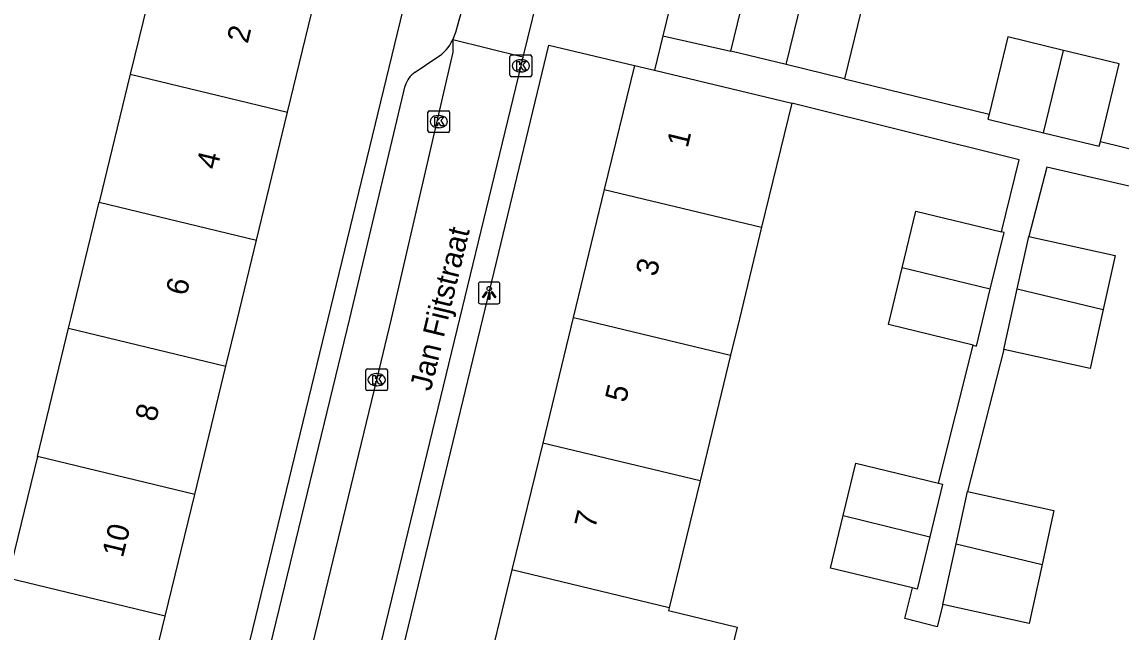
# Model space of a CAD drawing. Extents: x 162812 to 163818, y 381639 to 382470.
# Drawn here: x 163316.1 to 163366.7, y 382235.6 to 382263.7 of the extents above; entities that cross this region are included whole.
import ezdxf

# ---------------------------------------------------------------- set-up
doc = ezdxf.new("R2010")
doc.units = 0
for name, color, linetype in [('IMGEO_Kolk', 7, 'Continuous'), ('IMGEO_Lichtpunt', 7, 'Continuous'), ('IMGEO_Openbare_ruimte_label', 7, 'Continuous'), ('IMGEO_Pand', 7, 'Continuous'), ('IMGEO_Pand_nummerreeks', 7, 'Continuous'), ('IMGEO_Rijbaan_lokaal_open', 7, 'Continuous'), ('IMGEO_Voetpad_open', 7, 'Continuous')]:
    doc.layers.add(name, color=color, linetype=linetype)

msp = doc.modelspace()

# ---------------------------------------------------------------- linework, layer by layer
at = {"layer": 'IMGEO_Kolk'}
for p, q in [((163338.635, 382262.143), (163339.487, 382262.143)), ((163338.56, 382261.217), (163338.56, 382262.069)), ((163339.048, 382261.923), (163339.073, 382261.923)), ((163339.561, 382262.069), (163339.561, 382261.217)), ((163339.487, 382261.143), (163338.635, 382261.143)), ((163339.071, 382261.363), (163339.046, 382261.363)), ((163334.857, 382259.578), (163335.709, 382259.578)), ((163334.782, 382258.652), (163334.782, 382259.504)), ((163335.27, 382259.358), (163335.295, 382259.358)), ((163335.783, 382259.504), (163335.783, 382258.652)), ((163335.709, 382258.578), (163334.857, 382258.578)), ((163335.293, 382258.798), (163335.268, 382258.798)), ((163331.925, 382246.78), (163331.925, 382247.632)), ((163332, 382247.706), (163332.852, 382247.706)), ((163332.413, 382247.486), (163332.438, 382247.486)), ((163332.926, 382247.632), (163332.926, 382246.78)), ((163332.436, 382246.926), (163332.411, 382246.926)), ((163332.852, 382246.706), (163332, 382246.706))]:
    msp.add_line(p, q, dxfattribs=at)
for points in [[(163338.635, 382262.143), (163339.487, 382262.143)], [(163338.56, 382261.217), (163338.56, 382262.069)], [(163338.881, 382261.843), (163339.004, 382261.843), (163339.004, 382261.692), (163339.134, 382261.843), (163339.298, 382261.843), (163339.152, 382261.692), (163339.305, 382261.443), (163339.153, 382261.443), (163339.068, 382261.607), (163339.004, 382261.54), (163339.004, 382261.443), (163338.881, 382261.443), (163338.881, 382261.843)], [(163339.561, 382262.069), (163339.561, 382261.217)], [(163339.487, 382261.143), (163338.635, 382261.143)], [(163334.857, 382259.578), (163335.709, 382259.578)], [(163334.782, 382258.652), (163334.782, 382259.504)], [(163335.103, 382259.278), (163335.226, 382259.278), (163335.226, 382259.127), (163335.356, 382259.278), (163335.52, 382259.278), (163335.374, 382259.127), (163335.527, 382258.878), (163335.375, 382258.878), (163335.29, 382259.042), (163335.226, 382258.975), (163335.226, 382258.878), (163335.103, 382258.878), (163335.103, 382259.278)], [(163335.783, 382259.504), (163335.783, 382258.652)], [(163335.709, 382258.578), (163334.857, 382258.578)], [(163331.925, 382246.78), (163331.925, 382247.632)], [(163332, 382247.706), (163332.852, 382247.706)], [(163332.926, 382247.632), (163332.926, 382246.78)], [(163332.246, 382247.406), (163332.369, 382247.406), (163332.369, 382247.255), (163332.499, 382247.406), (163332.663, 382247.406), (163332.517, 382247.255), (163332.67, 382247.006), (163332.518, 382247.006), (163332.433, 382247.17), (163332.369, 382247.103), (163332.369, 382247.006), (163332.246, 382247.006), (163332.246, 382247.406)], [(163332.852, 382246.706), (163332, 382246.706)]]:
    msp.add_lwpolyline(points, dxfattribs=at)
for centre, start, end in [((163338.637, 382262.067), 91.552, 178.448), ((163338.637, 382262.067), 91.552, 178.448), ((163339.485, 382262.067), 1.552, 88.448), ((163339.485, 382262.067), 1.552, 88.448), ((163338.637, 382261.219), 181.552, 268.448), ((163338.637, 382261.219), 181.552, 268.448), ((163339.485, 382261.219), 271.552, 358.448), ((163339.485, 382261.219), 271.552, 358.448), ((163334.859, 382259.502), 91.552, 178.448), ((163334.859, 382259.502), 91.552, 178.448), ((163335.707, 382259.502), 1.552, 88.448), ((163335.707, 382259.502), 1.552, 88.448), ((163334.859, 382258.654), 181.552, 268.448), ((163334.859, 382258.654), 181.552, 268.448), ((163335.707, 382258.654), 271.552, 358.448), ((163335.707, 382258.654), 271.552, 358.448), ((163332.002, 382247.63), 91.552, 178.448), ((163332.002, 382247.63), 91.552, 178.448), ((163332.85, 382247.63), 1.552, 88.448), ((163332.85, 382247.63), 1.552, 88.448), ((163332.002, 382246.782), 181.552, 268.448), ((163332.002, 382246.782), 181.552, 268.448), ((163332.85, 382246.782), 271.552, 358.448), ((163332.85, 382246.782), 271.552, 358.448)]:
    msp.add_arc(centre, 0.0765, start, end, dxfattribs=at)
for centre, major_axis, ratio, start_param, end_param in [((163339.047, 382261.643), (-0.387, 0.002), 0.722429, 4.712389, 7.853982), ((163339.072, 382261.643), (-0.39, 0.002), 0.717154, 1.570796, 4.712389), ((163335.269, 382259.078), (-0.387, 0.002), 0.722429, 4.712389, 7.853982), ((163335.294, 382259.078), (-0.39, 0.002), 0.717154, 1.570796, 4.712389), ((163332.412, 382247.206), (-0.387, 0.002), 0.722429, 4.712389, 7.853982), ((163332.437, 382247.206), (-0.39, 0.002), 0.717154, 1.570796, 4.712389)]:
    msp.add_ellipse(centre, major_axis=major_axis, ratio=ratio, start_param=start_param, end_param=end_param, dxfattribs=at)
at = {"layer": 'IMGEO_Lichtpunt'}
for p, q in [((163337.103, 382251.599), (163337.103, 382250.792)), ((163337.103, 382251.599), (163337.103, 382250.792)), ((163338.005, 382251.694), (163337.197, 382251.694)), ((163338.005, 382251.694), (163337.197, 382251.694)), ((163338.099, 382250.792), (163338.099, 382251.599)), ((163338.099, 382250.792), (163338.099, 382251.599)), ((163337.197, 382250.698), (163338.005, 382250.698)), ((163337.197, 382250.698), (163338.005, 382250.698))]:
    msp.add_line(p, q, dxfattribs=at)
for points in [[(163337.477, 382251.263), (163337.516, 382251.235), (163337.328, 382250.973), (163337.29, 382251), (163337.477, 382251.263)], [(163337.579, 382251.215), (163337.626, 382251.215), (163337.626, 382250.893), (163337.579, 382250.893), (163337.579, 382251.215)], [(163337.689, 382251.235), (163337.727, 382251.262), (163337.914, 382251), (163337.875, 382250.972), (163337.689, 382251.235)]]:
    msp.add_lwpolyline(points, dxfattribs=at)
msp.add_circle((163337.602, 382251.397), 0.0994, dxfattribs=at)
for centre, start, end in [((163337.197, 382251.599), 90, 180), ((163337.197, 382251.599), 90, 180), ((163338.005, 382251.599), 0, 90), ((163338.005, 382251.599), 0, 90), ((163337.197, 382250.792), 180, 270), ((163337.197, 382250.792), 180, 270), ((163338.005, 382250.792), 270, 0), ((163338.005, 382250.792), 270, 360)]:
    msp.add_arc(centre, 0.0946, start, end, dxfattribs=at)
at = {"layer": 'IMGEO_Pand'}
for points in [[(163322.474, 382266.968), (163321.087, 382261.26)], [(163348.719, 382262.318), (163349.625, 382266.04), (163352.175, 382265.419)], [(163328.325, 382259.517), (163329.707, 382265.204)], [(163351.268, 382261.697), (163352.175, 382265.419)], [(163352.175, 382265.419), (163354.853, 382264.767), (163353.947, 382261.045)], [(163364.033, 382262.354), (163361.469, 382262.974), (163360.607, 382259.413)], [(163351.268, 382261.697), (163348.719, 382262.318)], [(163363.116, 382258.567), (163364.033, 382262.354)], [(163365.731, 382258.157), (163366.597, 382261.733), (163364.033, 382262.354)], [(163344.289, 382261.664), (163342.901, 382255.951)], [(163344.289, 382261.664), (163345.207, 382261.443)], [(163353.947, 382261.045), (163351.268, 382261.697)], [(163321.087, 382261.26), (163319.656, 382255.369)], [(163321.087, 382261.26), (163328.325, 382259.517)], [(163345.207, 382261.443), (163351.528, 382259.924)], [(163351.528, 382259.924), (163350.141, 382254.217)], [(163326.894, 382253.626), (163328.325, 382259.517)], [(163360.607, 382259.413), (163360.552, 382259.188), (163363.116, 382258.567)], [(163363.116, 382258.567), (163365.68, 382257.946), (163365.731, 382258.157)], [(163342.901, 382255.951), (163341.471, 382250.069)], [(163342.901, 382255.951), (163350.141, 382254.217)], [(163318.247, 382249.573), (163318.351, 382250), (163319.656, 382255.369)], [(163319.656, 382255.369), (163326.894, 382253.626)], [(163356.609, 382252.353), (163357.244, 382254.965), (163361.172, 382254.011)], [(163350.141, 382254.217), (163349.116, 382250), (163348.711, 382248.335)], [(163360.663, 382251.368), (163361.298, 382253.98), (163361.172, 382254.011)], [(163325.486, 382247.83), (163326.013, 382250), (163326.894, 382253.626)], [(163361.905, 382251.386), (163362.432, 382253.792)], [(163362.432, 382253.792), (163366.405, 382252.922), (163365.859, 382250.432)], [(163359.868, 382248.795), (163355.975, 382249.741), (163356.609, 382252.353)], [(163360.663, 382251.368), (163356.609, 382252.353)], [(163359.868, 382248.795), (163360.028, 382248.756), (163360.663, 382251.368)], [(163361.293, 382248.59), (163361.905, 382251.386)], [(163361.905, 382251.386), (163365.859, 382250.432)], [(163341.471, 382250.069), (163340.065, 382244.286)], [(163341.471, 382250.069), (163341.76, 382250), (163348.711, 382248.335)], [(163365.859, 382250.432), (163365.265, 382247.72), (163361.293, 382248.59)], [(163316.815, 382243.68), (163318.247, 382249.573)], [(163318.247, 382249.573), (163325.486, 382247.83)], [(163348.711, 382248.335), (163347.306, 382242.552)], [(163324.054, 382241.936), (163325.486, 382247.83)], [(163340.065, 382244.286), (163338.649, 382238.459)], [(163347.306, 382242.552), (163340.065, 382244.286)], [(163316.815, 382243.68), (163315.456, 382238.085)], [(163324.054, 382241.936), (163316.815, 382243.68)], [(163353.892, 382240.958), (163354.478, 382243.368), (163358.281, 382242.443)], [(163347.306, 382242.552), (163345.889, 382236.724)], [(163358.281, 382242.443), (163358.467, 382242.398), (163357.881, 382239.988)], [(163322.694, 382236.341), (163324.054, 382241.936)], [(163359.09, 382239.661), (163359.617, 382242.069)], [(163359.617, 382242.069), (163363.59, 382241.199), (163363.044, 382238.708)], [(163357.077, 382237.631), (163353.306, 382238.548), (163353.892, 382240.958)], [(163353.892, 382240.958), (163357.881, 382239.988)], [(163357.881, 382239.988), (163357.295, 382237.578), (163357.077, 382237.631)], [(163358.478, 382236.867), (163359.09, 382239.661)], [(163359.09, 382239.661), (163363.044, 382238.708)], [(163338.649, 382238.459), (163337.28, 382232.829)], [(163345.889, 382236.724), (163338.649, 382238.459)], [(163363.044, 382238.708), (163362.45, 382235.997), (163358.478, 382236.867)], [(163322.694, 382236.341), (163315.456, 382238.085)], [(163321.25, 382230.399), (163322.694, 382236.341)], [(163345.889, 382236.724), (163345.856, 382236.588), (163349.011, 382235.822), (163347.644, 382230.197), (163344.489, 382230.964)]]:
    msp.add_lwpolyline(points, dxfattribs=at)
at = {"layer": 'IMGEO_Rijbaan_lokaal_open'}
for points in [[(163335.923, 382262.841), (163336.07, 382263.186), (163336.691, 382265.461)], [(163339.789, 382264.679), (163339.145, 382262.043)], [(163335.923, 382262.841), (163335.923, 382262.268), (163333.095, 382250), (163332.423, 382247.206), (163325.569, 382218.972), (163321.838, 382204.251), (163321.731, 382204.132)], [(163339.145, 382262.043), (163335.923, 382262.841)], [(163339.145, 382262.043), (163339.056, 382261.643), (163336.233, 382250), (163331.974, 382232.436), (163324.797, 382202.931)]]:
    msp.add_lwpolyline(points, dxfattribs=at)
at = {"layer": 'IMGEO_Voetpad_open'}
for points in [[(163348.115, 382273.365), (163347.712, 382271.713), (163345.594, 382263.028)], [(163329.707, 382265.204), (163333.628, 382264.215), (163330.176, 382250), (163326.205, 382233.651), (163318.48, 382201.917), (163317.086, 382200.697)], [(163325.68, 382202.052), (163332.984, 382232.131), (163337.307, 382250), (163340.354, 382262.596), (163344.289, 382261.664)], [(163345.594, 382263.028), (163345.207, 382261.443)], [(163345.594, 382263.028), (163348.719, 382262.318)], [(163334.201, 382261.346), (163335.195, 382262.022)], [(163320.747, 382207.042), (163327.149, 382233.422), (163331.183, 382250.016), (163333.742, 382260.717)], [(163353.947, 382261.045), (163360.607, 382259.413)], [(163361.172, 382254.011), (163361.998, 382257.313), (163351.528, 382259.924)], [(163365.731, 382258.157), (163371.902, 382256.645)], [(163372.02, 382254.963), (163363.258, 382256.98), (163362.432, 382253.792)], [(163358.281, 382242.443), (163359.868, 382248.795)], [(163361.293, 382248.59), (163359.617, 382242.069)], [(163358.478, 382236.867), (163358.216, 382235.85), (163356.728, 382236.233), (163357.077, 382237.631)]]:
    msp.add_lwpolyline(points, dxfattribs=at)
for centre, radius, start, end in [((163334.207, 382263.634), 1.89, 301.5194, 335.2135), ((163334.732, 382260.476), 1.019, 121.419, 166.3423)]:
    msp.add_arc(centre, radius, start, end, dxfattribs=at)

# ---------------------------------------------------------------- texts
at = {"layer": 'IMGEO_Openbare_ruimte_label'}
msp.add_text('Jan Fijtstraat', height=1, rotation=76.4084, dxfattribs=at).set_placement((163334.913, 382246.644))
at = {"layer": 'IMGEO_Pand_nummerreeks'}
for s, rotation, p in [('2', 76.3426, (163326.488, 382262.629)), ('1', 76.3388, (163346.733, 382257.832)), ('4', 76.3426, (163325.079, 382256.831)), ('3', 76.3388, (163345.296, 382251.92)), ('6', 76.3426, (163323.67, 382251.031)), ('5', 76.3388, (163343.886, 382246.119)), ('8', 76.3426, (163322.262, 382245.235)), ('7', 76.3388, (163342.476, 382240.319)), ('10', 76.3426, (163320.744, 382238.988))]:
    msp.add_text(s, height=1, rotation=rotation, dxfattribs=at).set_placement(p)

doc.saveas('drawing.dxf')
